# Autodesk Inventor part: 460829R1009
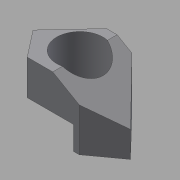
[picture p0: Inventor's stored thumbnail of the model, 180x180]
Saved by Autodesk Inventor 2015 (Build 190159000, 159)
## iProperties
Created: 2016-08
Part Number: 460829R1009
Material: 일반
Document SubType Name: Modeling
Designer: jio
Density: 1 g/cm^3
Appearance: 기본값
Author: jio
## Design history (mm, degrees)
sketch "스케치1"
  geometry: L1 (-9.387, 55)-(34, 55); L2 (34, 55)-(104.673, -18.184); L3 (104.673, -18.184)-(54, -55); L4 (54, -55)-(-34.842, -55); L5 (-34.842, -55)-(-70, -10); L6 (-70, -10)-(-9.387, 55); C1 r 39.5 at (0, 0); 1 further point
  constraints: 12 end point, 1 centre point, 1 coincident, 1 horizontal, 1 parallel
  dimensions: "d0" = 79 diameter of C1; "d1" = 104 horizontal distance of L1.end L5.end; "d2" = 45 distance from line of L4 L5.end; "d3" = 110 distance between parallel lines of L4 L1; "d4" = 70 horizontal distance of L5.end point (0, 0); "d5" = 55 distance from line of point (0, 0) L4; "d6" = 144 deg angle of L4 L3; "d7" = 128 deg angle of L4 L5; "d8" = 99 deg angle of L5 L6; "d9" = 134 deg angle of L2 L1; "d10" = 124 horizontal distance of L5.end L3.end
extrude "돌출1" new body sketch "스케치1" distance "d11" = 100; taper "d12" = 0 deg
sketch "스케치2"
  geometry: L1 (0, 100)-(88.842, 100) reference; L2 (68.842, 100)-(25.456, 100) reference; L3 (43.515, 100)-(139.515, 44.574); L4 (139.515, 0)-(139.515, 100) reference; L5 (43.515, 100)-(139.515, 100); L6 (88.842, 100)-(139.515, 100) reference; 1 further point
  constraints: 4 end point, 2 point on line, 1 collinear
  dimensions: "d13" = 96 distance from line of L3.start L4; "d14" = 30 deg angle of L3 L1
extrude "돌출2" cut sketch "스케치2" stored distance "d15" = 100; taper "d16" = 0 deg
sketch "스케치3"
  geometry: L1 (88.842, 0)-(0, 0) reference; L2 (-35.158, 40)-(78.842, 40); L3 (78.842, 40)-(78.842, 0); L4 (78.842, 0)-(-35.158, 0); L5 (-35.158, 0)-(-35.158, 40); L6 (-35.158, 0)-(-35.158, 100) reference; 1 further point
  constraints: 8 end point, 2 collinear, 2 parallel, 1 horizontal, 1 perpendicular
  dimensions: "d17" = 40 distance between parallel lines of L2 L4; "d18" = 114 distance between parallel lines of L3 L5
extrude "돌출3" cut sketch "스케치3" distance "d19" = 70; taper "d20" = 0 deg
node "솔리드1"
